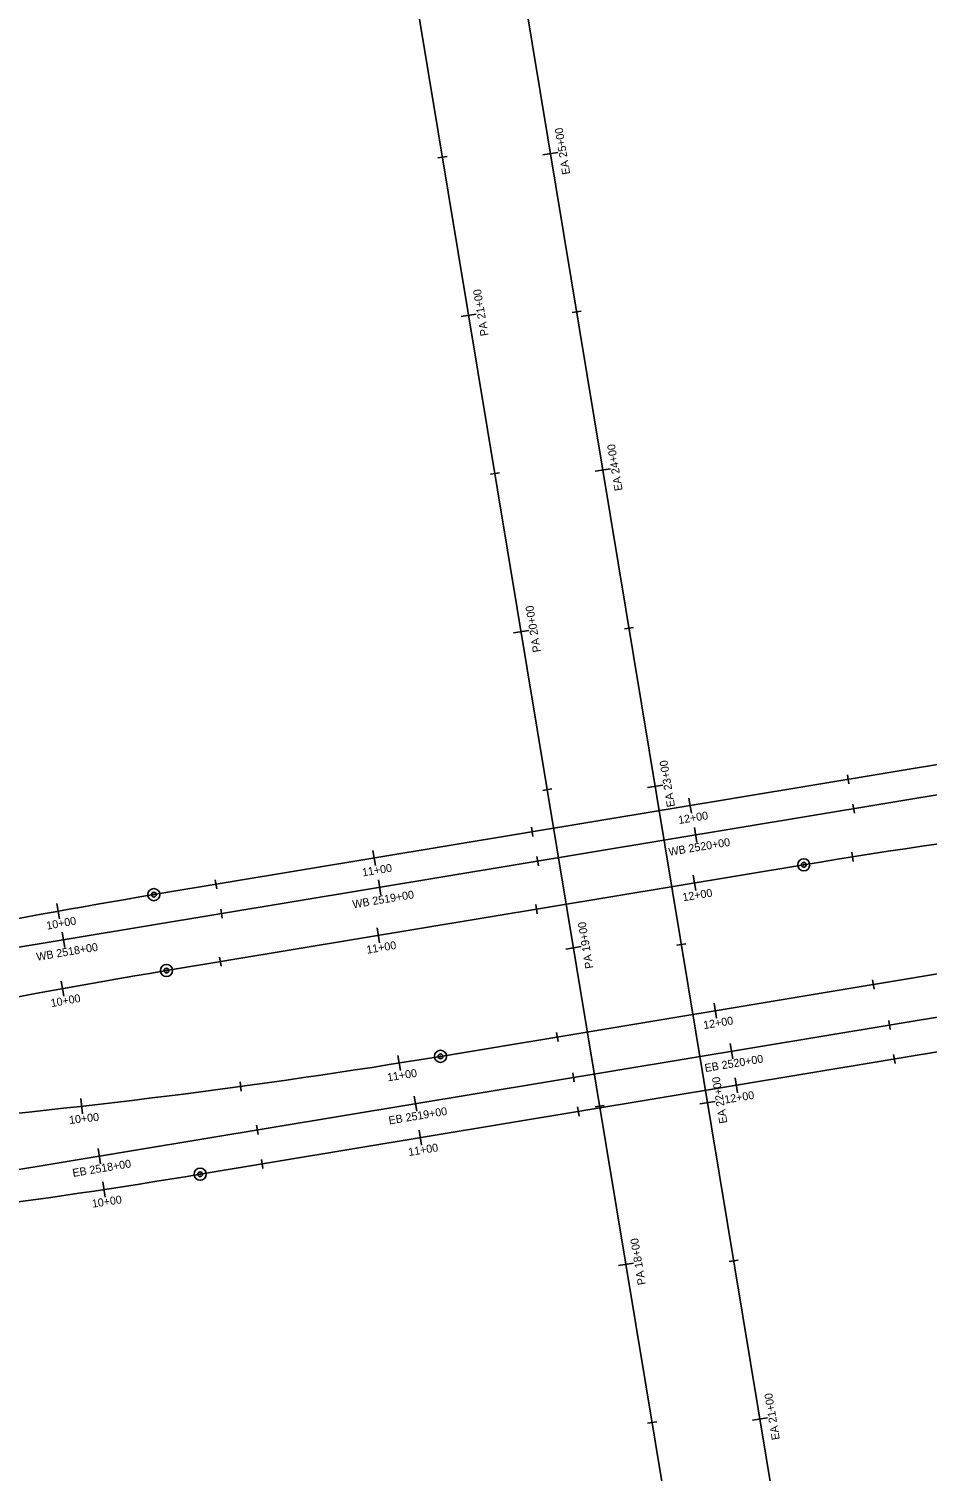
# Model space of a CAD drawing. Extents: x 950864 to 953360, y 1126381 to 1128045.
# Drawn here: x 951848.2 to 952128.6, y 1127119 to 1127568.8 of the extents above; entities that cross this region are included whole.
import ezdxf

# ---------------------------------------------------------------- set-up
doc = ezdxf.new("R2010")
doc.units = 0
for name, color, linetype in [('Existing', 7, 'Continuous'), ('LFILL_P', 7, 'Continuous'), ('North Crossover', 7, 'Continuous'), ('Proposed', 7, 'Continuous')]:
    doc.layers.add(name, color=color, linetype=linetype)

msp = doc.modelspace()

# ---------------------------------------------------------------- linework, layer by layer
at = {"layer": 'Existing'}
for p, q in [((952101.78, 1126982.28), (951986.82, 1127675.69)), ((950872.52, 1127121.15), (953338.85, 1127530.05)), ((950883.69, 1127053.72), (953350.03, 1127462.62))]:
    msp.add_line(p, q, dxfattribs=at)
for points in [[(952008.63, 1127529.49), (952013.36, 1127530.28)], [(952017.75, 1127480.32), (952020.59, 1127480.8)], [(952024.98, 1127430.84), (952029.72, 1127431.63)], [(952034.11, 1127381.67), (952036.95, 1127382.14)], [(952041.34, 1127332.19), (952046.07, 1127332.97)], [(952105.45, 1127327.02), (952105.92, 1127324.18)], [(952055.96, 1127319.79), (952056.75, 1127315.05)], [(952006.79, 1127310.66), (952007.26, 1127307.82)], [(951957.31, 1127303.43), (951958.09, 1127298.7)], [(951908.14, 1127294.31), (951908.61, 1127291.47)], [(951858.66, 1127287.08), (951859.44, 1127282.34)], [(952050.46, 1127283.02), (952053.3, 1127283.49)], [(952116.63, 1127259.59), (952117.1, 1127256.75)], [(952067.14, 1127252.36), (952067.93, 1127247.62)], [(952017.97, 1127243.23), (952018.44, 1127240.39)], [(951968.49, 1127236), (951969.27, 1127231.27)], [(952057.69, 1127233.53), (952062.43, 1127234.32)], [(951919.32, 1127226.88), (951919.79, 1127224.04)], [(951869.84, 1127219.65), (951870.62, 1127214.91)], [(952066.82, 1127184.36), (952069.66, 1127184.84)], [(952074.05, 1127134.88), (952078.79, 1127135.67)]]:
    msp.add_lwpolyline(points, dxfattribs=at)
at = {"layer": 'LFILL_P'}
for p, q in [((951976.7, 1127248.38), (952619.55, 1127354.96)), ((951901.7, 1127211.62), (952623.47, 1127331.29))]:
    msp.add_line(p, q, dxfattribs=at)
for points in [[(952111.56, 1127272.2), (952112.03, 1127269.36)], [(952062.08, 1127264.97), (952062.86, 1127260.24)], [(952012.91, 1127255.85), (952013.38, 1127253.01)], [(951963.43, 1127248.66), (951964.19, 1127243.92)], [(952118.13, 1127248.96), (952118.6, 1127246.12)], [(951914.15, 1127240.4), (951914.54, 1127237.55)], [(952068.65, 1127241.73), (952069.44, 1127237)], [(951864.46, 1127235.2), (951865, 1127230.43)], [(952019.48, 1127232.61), (952019.95, 1127229.77)], [(951970, 1127225.38), (951970.78, 1127220.64)], [(951920.83, 1127216.25), (951921.3, 1127213.41)], [(951871.34, 1127209.24), (951872.06, 1127204.49)]]:
    msp.add_lwpolyline(points, dxfattribs=at)
for centre, radius in [((951976.7, 1127248.38), 1.89), ((951976.7, 1127248.38), 0.744), ((951976.7, 1127248.38), 0.154), ((951901.7, 1127211.62), 1.89), ((951901.7, 1127211.62), 0.744), ((951901.7, 1127211.62), 0.154)]:
    msp.add_circle(centre, radius, dxfattribs=at)
for centre, radius, start in [((951622.6, 1129384.23), 2165, 270.26513), ((951543.67, 1129371.14), 2189, 275.4013)]:
    msp.add_arc(centre, radius, start, 279.4135, dxfattribs=at)
at = {"layer": 'North Crossover'}
for p, q in [((951887.25, 1127298.82), (952366.98, 1127378.36)), ((951891.17, 1127275.14), (952090.08, 1127308.12))]:
    msp.add_line(p, q, dxfattribs=at)
for points in [[(952103.72, 1127336.17), (952104.2, 1127333.33)], [(952054.24, 1127328.94), (952055.03, 1127324.21)], [(952005.07, 1127319.82), (952005.54, 1127316.97)], [(951955.59, 1127312.58), (951956.37, 1127307.85)], [(952105.09, 1127312.01), (952105.54, 1127309.17)], [(951906.42, 1127303.46), (951906.89, 1127300.62)], [(952055.58, 1127304.84), (952056.37, 1127300.1)], [(951856.94, 1127296.02), (951857.79, 1127291.29)], [(952006.41, 1127295.71), (952006.88, 1127292.87)], [(951956.93, 1127288.48), (951957.71, 1127283.74)], [(951907.76, 1127279.35), (951908.23, 1127276.51)], [(951858.28, 1127271.87), (951859.14, 1127267.15)]]:
    msp.add_lwpolyline(points, dxfattribs=at)
for centre, radius in [((952090.08, 1127308.12), 1.88), ((952090.08, 1127308.12), 0.747), ((952090.08, 1127308.12), 0.156), ((951887.25, 1127298.82), 1.89), ((951887.25, 1127298.82), 0.744), ((951887.25, 1127298.82), 0.154), ((951891.17, 1127275.14), 1.89), ((951891.17, 1127275.14), 0.744), ((951891.17, 1127275.14), 0.154)]:
    msp.add_circle(centre, radius, dxfattribs=at)
for centre, radius, start, end in [((952444.18, 1125172.28), 2165, 90.38393, 99.4135), ((952245.27, 1125139.3), 2189, 99.4135, 103.15104), ((952245.27, 1125139.3), 2165, 99.4135, 108.44308)]:
    msp.add_arc(centre, radius, start, end, dxfattribs=at)
at = {"layer": 'Proposed'}
msp.add_line((952074.92, 1126940.23), (951969.89, 1127573.74), dxfattribs=at)
for points in [[(951975.92, 1127528.59), (951978.76, 1127529.06)], [(951983.15, 1127479.11), (951987.88, 1127479.89)], [(951992.27, 1127429.94), (951995.12, 1127430.41)], [(951999.51, 1127380.46), (952004.24, 1127381.24)], [(952008.63, 1127331.29), (952011.47, 1127331.76)], [(952015.86, 1127281.8), (952020.6, 1127282.59)], [(952024.99, 1127232.63), (952027.83, 1127233.1)], [(952032.22, 1127183.15), (952036.95, 1127183.93)], [(952041.34, 1127133.98), (952044.18, 1127134.45)]]:
    msp.add_lwpolyline(points, dxfattribs=at)

# ---------------------------------------------------------------- texts
at = {"layer": 'Existing'}
for s, rotation, p in [('EA 25+00', 99.4135, (952017.2, 1127523.59)), ('EA 24+00', 99.4135, (952033.55, 1127424.93)), ('EA 23+00', 99.4135, (952049.9, 1127326.32)), ('WB 2520+00', 9.4135, (952048.11, 1127310.9)), ('WB 2519+00', 9.4135, (951949.45, 1127294.54)), ('WB 2518+00', 9.4135, (951850.8, 1127278.18)), ('EB 2520+00', 9.4135, (952059.37, 1127243.48)), ('EA 22+00', 99.4135, (952066.26, 1127227.63)), ('EB 2519+00', 9.4135, (951960.72, 1127227.13)), ('EB 2518+00', 9.4135, (951862.06, 1127210.77)), ('EA 21+00', 99.4135, (952082.62, 1127128.97))]:
    msp.add_text(s, height=2.496, rotation=rotation, dxfattribs=at).set_placement(p)
at = {"layer": 'LFILL_P'}
for s, rotation, p in [('12+00', 9.4135, (952058.96, 1127256.86)), ('11+00', 9.0679, (951960.26, 1127240.57)), ('12+00', 9.4135, (952065.53, 1127233.63)), ('10+00', 6.4214, (951860.92, 1127227.26)), ('11+00', 9.4135, (951966.88, 1127217.27)), ('10+00', 8.6184, (951868.11, 1127201.17))]:
    msp.add_text(s, height=2.496, rotation=rotation, dxfattribs=at).set_placement(p)
at = {"layer": 'North Crossover'}
for s, rotation, p in [('12+00', 9.4135, (952051.12, 1127320.83)), ('11+00', 9.4135, (951952.47, 1127304.48)), ('12+00', 9.4135, (952052.46, 1127296.73)), ('10+00', 10.2073, (951853.93, 1127287.87)), ('11+00', 9.4135, (951953.81, 1127280.37)), ('10+00', 10.2854, (951855.29, 1127263.72))]:
    msp.add_text(s, height=2.496, rotation=rotation, dxfattribs=at).set_placement(p)
at = {"layer": 'Proposed'}
for s, p in [('PA 21+00', (951991.71, 1127473.24)), ('PA 20+00', (952008.07, 1127374.58)), ('PA 19+00', (952024.42, 1127275.93)), ('PA 18+00', (952040.78, 1127177.28))]:
    msp.add_text(s, height=2.496, rotation=99.4135, dxfattribs=at).set_placement(p)

doc.saveas('drawing.dxf')
